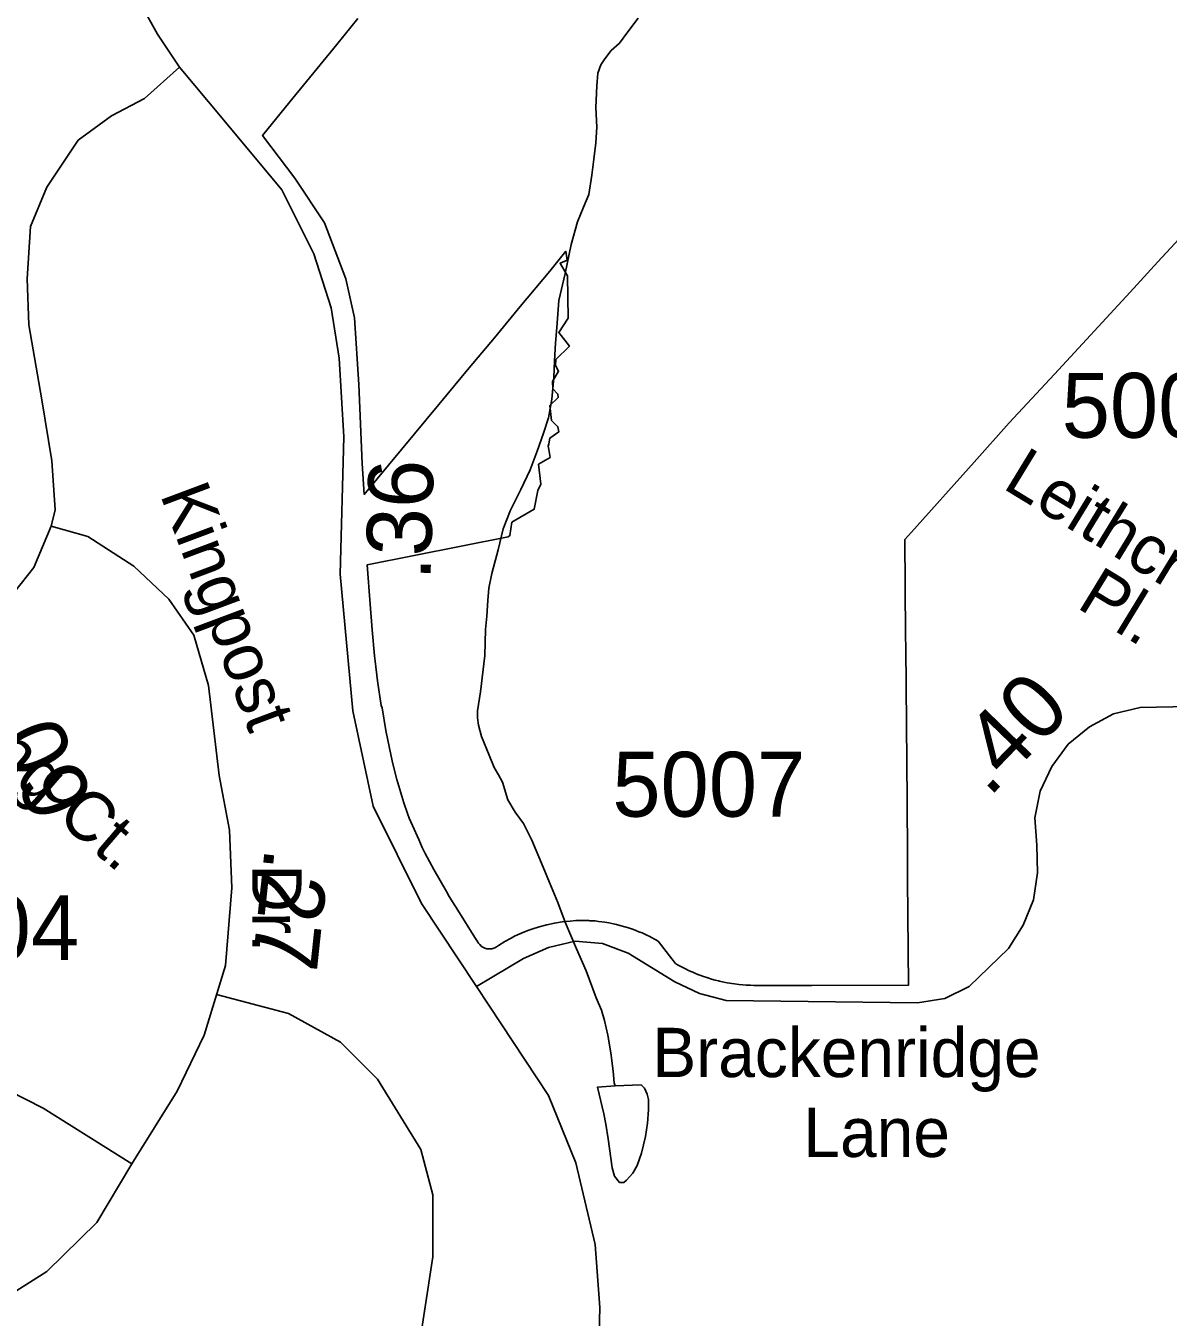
# Model space of a CAD drawing. Extents: x 2001466 to 2224147, y 644118 to 847247.
# Drawn here: x 2063438 to 2065640, y 689110 to 691599 of the extents above; entities that cross this region are included whole.
import ezdxf

# ---------------------------------------------------------------- set-up
doc = ezdxf.new("R2010")
doc.units = 0
for name, color, linetype in [('Exist Boundary Political City Limit New', 7, 'Continuous'), ('Exist Hydrographic Misc Water Feature', 7, 'Continuous'), ('Exist Road Non-System Type 51', 7, 'Continuous'), ('Exist Road Secondary Mileage Hundredths English Label', 7, 'Continuous'), ('Exist Road Secondary Type 51 Attributed', 7, 'Continuous'), ('Exist Road Secondary Type 51 Label', 7, 'Continuous'), ('Exist Road Secondary Type 51 Number Label', 7, 'Continuous'), ('Map Preparation Boundary City Limit Buffer Line', 7, 'Continuous')]:
    doc.layers.add(name, color=color, linetype=linetype)

msp = doc.modelspace()

# ---------------------------------------------------------------- linework, layer by layer
at = {"layer": 'Exist Boundary Political City Limit New'}
for points in [[(2064077.9, 691613), (2064037.2, 691563.1), (2063946.9, 691452.2), (2063894.1, 691387.4), (2063956.2, 691305.4), (2064013.8, 691219.3), (2064055, 691111.1), (2064071.1, 691036.2), (2064079.9, 690907.6), (2064086.2, 690755.5), (2064090.1, 690695.9), (2064233.9, 690869.1), (2064292.6, 690939.7), (2064341, 690998), (2064390.8, 691057.8), (2064447.6, 691126.3), (2064478.8, 691164.7), (2064481.5, 691147.5), (2064476.9, 691145.5), (2064467.8, 691141.4), (2064471.2, 691135.6), (2064482.2, 691117.4), (2064483.4, 691035.4), (2064465.5, 691007.7), (2064485.8, 690981.7), (2064459.5, 690955.7), (2064458.6, 690944.7), (2064464.9, 690933.3), (2064453.1, 690913.5), (2064454, 690899.5), (2064463.6, 690889.4), (2064464, 690882.4)], [(2064690, 689792.1), (2064692.1, 689790.8), (2064695.6, 689788.9), (2064700.4, 689786.2), (2064705.8, 689783.4), (2064710.6, 689780.9), (2064714.2, 689779.2), (2064719.8, 689776.7), (2064723.4, 689775.1), (2064727.5, 689773.3), (2064733.5, 689770.9), (2064739.1, 689768.8), (2064743.9, 689767.1), (2064748.6, 689765.4), (2064752.4, 689764.2), (2064759.5, 689762), (2064766.8, 689760), (2064773.1, 689758.4), (2064774.8, 689758), (2064783.4, 689756.1), (2064789.8, 689754.8), (2064795.1, 689753.9), (2064799, 689753.2), (2064804, 689752.5), (2064812, 689751.5), (2064819.9, 689750.8), (2064826.4, 689750.2), (2064834.4, 689749.9), (2064841.4, 689749.7), (2064845.1, 689749.7), (2064953.2, 689749.8), (2065139.2, 689750.1), (2065137.6, 689954.1), (2065137.2, 690000), (2065136.4, 690106), (2065135.1, 690253), (2065133.9, 690401), (2065133.6, 690422.9), (2065132.9, 690520), (2065132.1, 690609), (2065144.8, 690623.2), (2065265.6, 690758), (2065333.5, 690833.8), (2065411.6, 690918.2), (2065420.4, 690927.8), (2065566.4, 691085.7), (2065620, 691143.9), (2065726.4, 691259.4)], [(2064464, 690882.4), (2064448.2, 690867.1), (2064451.2, 690838.2), (2064463.5, 690826.4), (2064465.2, 690816.5), (2064448, 690804.6), (2064445.8, 690793.4), (2064444.9, 690788.8), (2064446, 690782.4), (2064448.8, 690767.2), (2064426.2, 690754.2), (2064430.4, 690715.4), (2064425, 690703.5), (2064418, 690667.2), (2064374.8, 690642.2), (2064370.9, 690616.6), (2064367.6, 690614.2), (2064096, 690560.4), (2064101.6, 690484.7), (2064105.6, 690435.2), (2064110.2, 690384.8), (2064111.5, 690374.4), (2064116, 690336.6), (2064123.1, 690288.9), (2064124.5, 690284.4), (2064131.8, 690240.9), (2064141.9, 690191.8), (2064145.5, 690176.6), (2064152.8, 690146.8), (2064166.2, 690101.4), (2064173.8, 690081.1), (2064177.1, 690072), (2064182.9, 690058.1), (2064195.1, 690031.1), (2064201.8, 690015.4), (2064207.9, 690004.2), (2064216.1, 689988.6), (2064224.4, 689973.4), (2064248.5, 689931), (2064254.2, 689921), (2064273.9, 689889.5), (2064300.2, 689847.1), (2064310.4, 689831.4), (2064312.8, 689828.3), (2064315.6, 689825.6), (2064318.9, 689823.3), (2064322.5, 689821.6), (2064326.2, 689820.5), (2064330.1, 689820), (2064334.1, 689820.1), (2064334.9, 689820.2), (2064335.9, 689820.4), (2064338, 689820.8), (2064340.2, 689821.6), (2064341.6, 689822.1), (2064345.1, 689824.1), (2064349.1, 689826.7), (2064361, 689834.1), (2064373.4, 689840.9), (2064380.1, 689844.4), (2064385.9, 689847.1), (2064398.8, 689852.8), (2064407.5, 689856.4), (2064413, 689858.1), (2064427.4, 689862.8), (2064442.1, 689866.6), (2064456.9, 689869.7), (2064471.9, 689872), (2064487, 689873.6), (2064497.9, 689874.8), (2064499.9, 689874.8), (2064503.9, 689874.9), (2064510.4, 689875), (2064515.9, 689874.9), (2064523.4, 689874.6), (2064525.1, 689874.5), (2064527.9, 689874.4), (2064535.4, 689873.9), (2064541.9, 689873.1), (2064548.2, 689872.4), (2064554.2, 689871.5), (2064561.6, 689870.2), (2064570.5, 689868.5), (2064573.4, 689867.9), (2064576.2, 689867.2), (2064583.1, 689865.5), (2064592.2, 689862.9), (2064599.4, 689860.7), (2064608.9, 689857.4), (2064614, 689855.5), (2064619.6, 689853.3), (2064625.6, 689850.8), (2064632.1, 689847.8), (2064635.2, 689846.3), (2064640.8, 689843.7), (2064644.2, 689841.8), (2064651.2, 689838), (2064656.9, 689834.8), (2064683.2, 689800.8), (2064690, 689792.1)]]:
    msp.add_lwpolyline(points, dxfattribs=at)
at = {"layer": 'Exist Hydrographic Misc Water Feature'}
for points in [[(2064573.7, 689556), (2064571.8, 689562), (2064570, 689584.2), (2064565.7, 689620.1), (2064559.9, 689653.9), (2064553.6, 689682), (2064547.4, 689702), (2064537.4, 689725.8), (2064517.7, 689777.9), (2064499.4, 689820), (2064477.7, 689871.9), (2064463.6, 689909.8), (2064447.4, 689947.9), (2064435.3, 689977.8), (2064412.9, 690029.8), (2064396.9, 690061.5), (2064381.1, 690083.7), (2064366.8, 690107.4), (2064356.7, 690141.4), (2064348.9, 690155.5), (2064340.5, 690169.4), (2064331.1, 690193.5), (2064316.5, 690229.4), (2064310.4, 690251.4), (2064308.5, 690265.5), (2064308.7, 690279.2), (2064314.3, 690315.3), (2064322.7, 690385.5), (2064324.1, 690435.5), (2064326.4, 690461.5), (2064328.4, 690491.3), (2064330.3, 690515.3), (2064336.2, 690543.6), (2064348.1, 690589.3), (2064357.7, 690629.6), (2064371.9, 690665.6), (2064391.8, 690705.5), (2064409.8, 690743.3), (2064423.6, 690779.4), (2064435.7, 690813.7), (2064445.3, 690843.4), (2064451.7, 690879.4), (2064455.4, 690921.4), (2064457.2, 690953.5), (2064459, 690987.4), (2064461.1, 691017.5), (2064465.2, 691069.6), (2064477.3, 691121.7), (2064489, 691177.5), (2064501.1, 691221.5), (2064512.6, 691249.8), (2064523, 691273.8), (2064528.8, 691311.4), (2064532.7, 691341.7), (2064536.6, 691373.5), (2064538.6, 691403.6), (2064536.6, 691441.7), (2064538.4, 691483.6), (2064540.2, 691507.6), (2064546.4, 691523.7), (2064554.2, 691535.5), (2064566.3, 691551.5), (2064582.3, 691565.7), (2064598.3, 691587.7), (2064618.4, 691613.8)], [(2064573.7, 689556), (2064539.8, 689553.9), (2064551.9, 689502.1), (2064555.8, 689482.1), (2064560.1, 689453.8), (2064568.3, 689398.3), (2064572.4, 689382.2), (2064582.3, 689370.2), (2064590.3, 689370.2), (2064596, 689374.2), (2064608.1, 689388.2), (2064616.1, 689402.4), (2064624.3, 689426.3), (2064632.3, 689458.4), (2064636, 689484.1), (2064637.8, 689510.2), (2064638.3, 689530), (2064635.6, 689540.2), (2064630.1, 689552), (2064623.7, 689558.2), (2064573.7, 689556)]]:
    msp.add_lwpolyline(points, dxfattribs=at)
at = {"layer": 'Exist Road Non-System Type 51'}
msp.add_lwpolyline([(2063805.6, 689732.4), (2063944.2, 689695.4), (2064044.4, 689640.5), (2064115.5, 689569.3), (2064199.5, 689433.5), (2064222.1, 689346.2), (2064222.1, 689226.5), (2064176.9, 688929)], dxfattribs=at)
at = {"layer": 'Exist Road Secondary Type 51 Attributed'}
for points in [[(2063100.7, 692634.2), (2063227, 692501.2), (2063335.4, 692367.9), (2063398.1, 692269.1), (2063467, 692146.5), (2063519.3, 692011.6), (2063581.2, 691846.5), (2063660.1, 691639.6), (2063691.6, 691582.8), (2063734.2, 691519.6)], [(2063734.2, 691519.6), (2063666.4, 691458.8), (2063603.3, 691425.6), (2063538.6, 691378.3), (2063478.6, 691288.3), (2063447, 691212.5), (2063440.7, 691111.4), (2063443.5, 691023), (2063468.7, 690878.5), (2063488.1, 690760.9), (2063494.4, 690666.1), (2063486.5, 690634.5)], [(2063734.2, 691519.6), (2063819.4, 691417), (2063931.5, 691282.7), (2063993, 691159.6), (2064026.2, 691055.4), (2064041.6, 690958.2), (2064051, 690806.7), (2064043.9, 690542.2), (2064068, 690279.2), (2064107.4, 690095.3), (2064200.5, 689907.4), (2064306.6, 689747.5)], [(2063486.5, 690634.5), (2063453.4, 690554.8), (2063392.6, 690478.2), (2063294.8, 690415.8), (2063155.5, 690356.6)], [(2063486.5, 690634.5), (2063557.1, 690614.8), (2063646.3, 690557.9), (2063713.3, 690494), (2063761.8, 690424.5), (2063790.2, 690327.4), (2063810.8, 690154.5), (2063830.5, 690048.7), (2063835.2, 689938.1), (2063822.6, 689788.1), (2063781.6, 689653.9), (2063729.9, 689545.7), (2063642.3, 689406)], [(2063155.5, 690356.6), (2063074.2, 690323.4), (2062979.6, 690274.5), (2062919.6, 690197.1), (2062881.7, 690094.5), (2062872.3, 690007.6), (2062878.2, 689920.8), (2062912.5, 689845.8), (2062976.4, 689765.2), (2063090, 689705.2), (2063305.4, 689597.1), (2063471.1, 689513.4), (2063642.3, 689406)], [(2064306.6, 689747.5), (2064397, 689801.8), (2064445.4, 689822.9), (2064496.8, 689834.7), (2064549.4, 689830.4), (2064598.9, 689812), (2064689, 689756.9), (2064736.6, 689734.1), (2064787.7, 689720.7), (2065156.9, 689716.2), (2065209.1, 689724.6), (2065256.5, 689747.8), (2065332.3, 689821.2), (2065360.1, 689866.1), (2065380.5, 689914.8), (2065388.2, 689967), (2065386.6, 690019.8), (2065382.9, 690072.4), (2065393.2, 690124.2), (2065415.7, 690171.9), (2065447.1, 690214.4), (2065487.9, 690247.9), (2065534.4, 690272.8), (2065585.7, 690285.5), (2065744, 690288.8)], [(2064306.6, 689747.5), (2064354, 689676), (2064445.1, 689537.9), (2064498, 689407.6), (2064535.1, 689250.5), (2064544.5, 689128.9), (2064539.8, 688956.7), (2064517.3, 688753.8), (2064495.6, 688554.9), (2064480.6, 688417.5)], [(2063642.3, 689406), (2063574.9, 689293.1), (2063478.6, 689198.3), (2063365, 689127.3), (2063237.2, 689086.2), (2063095.1, 689076.8), (2062954.7, 689100.4), (2062794.1, 689151), (2062684.5, 689164.4), (2062584.3, 689154.1), (2062486.8, 689132)]]:
    msp.add_lwpolyline(points, dxfattribs=at)
at = {"layer": 'Map Preparation Boundary City Limit Buffer Line'}
for points in [[(2064077.9, 691613), (2064037.2, 691563.1), (2063946.9, 691452.2), (2063894.1, 691387.4), (2063956.2, 691305.4), (2064013.8, 691219.3), (2064055, 691111.1), (2064071.1, 691036.2), (2064079.9, 690907.6), (2064086.2, 690755.5), (2064090.1, 690695.9), (2064233.9, 690869.1), (2064292.6, 690939.7), (2064341, 690998), (2064390.8, 691057.8), (2064447.6, 691126.3), (2064478.8, 691164.7), (2064481.5, 691147.5), (2064476.9, 691145.5), (2064467.8, 691141.4), (2064471.2, 691135.6), (2064482.2, 691117.4), (2064483.4, 691035.4), (2064465.5, 691007.7), (2064485.8, 690981.7), (2064459.5, 690955.7), (2064458.6, 690944.7), (2064464.9, 690933.3), (2064453.1, 690913.5), (2064454, 690899.5), (2064463.6, 690889.4), (2064464, 690882.4)], [(2064690, 689792.1), (2064692.1, 689790.8), (2064695.6, 689788.9), (2064700.4, 689786.2), (2064705.8, 689783.4), (2064710.6, 689780.9), (2064714.2, 689779.2), (2064719.8, 689776.7), (2064723.4, 689775.1), (2064727.5, 689773.3), (2064733.5, 689770.9), (2064739.1, 689768.8), (2064743.9, 689767.1), (2064748.6, 689765.4), (2064752.4, 689764.2), (2064759.5, 689762), (2064766.8, 689760), (2064773.1, 689758.4), (2064774.8, 689758), (2064783.4, 689756.1), (2064789.8, 689754.8), (2064795.1, 689753.9), (2064799, 689753.2), (2064804, 689752.5), (2064812, 689751.5), (2064819.9, 689750.8), (2064826.4, 689750.2), (2064834.4, 689749.9), (2064841.4, 689749.7), (2064845.1, 689749.7), (2064953.2, 689749.8), (2065139.2, 689750.1), (2065137.6, 689954.1), (2065137.2, 690000), (2065136.4, 690106), (2065135.1, 690253), (2065133.9, 690401), (2065133.6, 690422.9), (2065132.9, 690520), (2065132.1, 690609), (2065144.8, 690623.2), (2065265.6, 690758), (2065333.5, 690833.8), (2065411.6, 690918.2), (2065420.4, 690927.8), (2065566.4, 691085.7), (2065620, 691143.9), (2065726.4, 691259.4)], [(2064464, 690882.4), (2064448.2, 690867.1), (2064451.2, 690838.2), (2064463.5, 690826.4), (2064465.2, 690816.5), (2064448, 690804.6), (2064445.8, 690793.4), (2064444.9, 690788.8), (2064446, 690782.4), (2064448.8, 690767.2), (2064426.2, 690754.2), (2064430.4, 690715.4), (2064425, 690703.5), (2064418, 690667.2), (2064374.8, 690642.2), (2064370.9, 690616.6), (2064367.6, 690614.2), (2064096, 690560.4), (2064101.6, 690484.7), (2064105.6, 690435.2), (2064110.2, 690384.8), (2064111.5, 690374.4), (2064116, 690336.6), (2064123.1, 690288.9), (2064124.5, 690284.4), (2064131.8, 690240.9), (2064141.9, 690191.8), (2064145.5, 690176.6), (2064152.8, 690146.8), (2064166.2, 690101.4), (2064173.8, 690081.1), (2064177.1, 690072), (2064182.9, 690058.1), (2064195.1, 690031.1), (2064201.8, 690015.4), (2064207.9, 690004.2), (2064216.1, 689988.6), (2064224.4, 689973.4), (2064248.5, 689931), (2064254.2, 689921), (2064273.9, 689889.5), (2064300.2, 689847.1), (2064310.4, 689831.4), (2064312.8, 689828.3), (2064315.6, 689825.6), (2064318.9, 689823.3), (2064322.5, 689821.6), (2064326.2, 689820.5), (2064330.1, 689820), (2064334.1, 689820.1), (2064334.9, 689820.2), (2064335.9, 689820.4), (2064338, 689820.8), (2064340.2, 689821.6), (2064341.6, 689822.1), (2064345.1, 689824.1), (2064349.1, 689826.7), (2064361, 689834.1), (2064373.4, 689840.9), (2064380.1, 689844.4), (2064385.9, 689847.1), (2064398.8, 689852.8), (2064407.5, 689856.4), (2064413, 689858.1), (2064427.4, 689862.8), (2064442.1, 689866.6), (2064456.9, 689869.7), (2064471.9, 689872), (2064487, 689873.6), (2064497.9, 689874.8), (2064499.9, 689874.8), (2064503.9, 689874.9), (2064510.4, 689875), (2064515.9, 689874.9), (2064523.4, 689874.6), (2064525.1, 689874.5), (2064527.9, 689874.4), (2064535.4, 689873.9), (2064541.9, 689873.1), (2064548.2, 689872.4), (2064554.2, 689871.5), (2064561.6, 689870.2), (2064570.5, 689868.5), (2064573.4, 689867.9), (2064576.2, 689867.2), (2064583.1, 689865.5), (2064592.2, 689862.9), (2064599.4, 689860.7), (2064608.9, 689857.4), (2064614, 689855.5), (2064619.6, 689853.3), (2064625.6, 689850.8), (2064632.1, 689847.8), (2064635.2, 689846.3), (2064640.8, 689843.7), (2064644.2, 689841.8), (2064651.2, 689838), (2064656.9, 689834.8), (2064683.2, 689800.8), (2064690, 689792.1)]]:
    msp.add_lwpolyline(points, dxfattribs=at)

# ---------------------------------------------------------------- texts
at = {"layer": 'Exist Road Secondary Mileage Hundredths English Label'}
for s, rotation, p in [('.36', 88.4621, (2064217.8, 690529.2)), ('.40', 45.9468, (2065294.4, 690110.4)), ('.09', 294.1701, (2063361.6, 690268.3)), ('.27', 263.8878, (2063898.9, 690017.7))]:
    msp.add_text(s, height=125, rotation=rotation, dxfattribs=at).set_placement(p)
at = {"layer": 'Exist Road Secondary Type 51 Label'}
for s, rotation, p in [('Leithcroft', 328.5815, (2065318.2, 690709.1)), ('Kingpost', 290.5558, (2063696.1, 690696)), (' Pl.', 328.5815, (2065430.9, 690497.3)), ('Oaksong Ct.', 319.2324, (2063082.4, 690426)), ('Dr.', 270, (2063874.3, 689983))]:
    msp.add_text(s, height=95, rotation=rotation, dxfattribs=at).set_placement(p)
for s, p in [('Brackenridge', (2064645.4, 689573)), ('Lane', (2064936.6, 689419.1))]:
    msp.add_text(s, height=95, dxfattribs=at).set_placement(p)
at = {"layer": 'Exist Road Secondary Type 51 Number Label'}
for s, p in [('5008', (2065434.6, 690805.1)), ('5007', (2064568.4, 690074.9)), ('4704', (2063168.7, 689798.6))]:
    msp.add_text(s, height=125, dxfattribs=at).set_placement(p)

doc.saveas('drawing.dxf')
